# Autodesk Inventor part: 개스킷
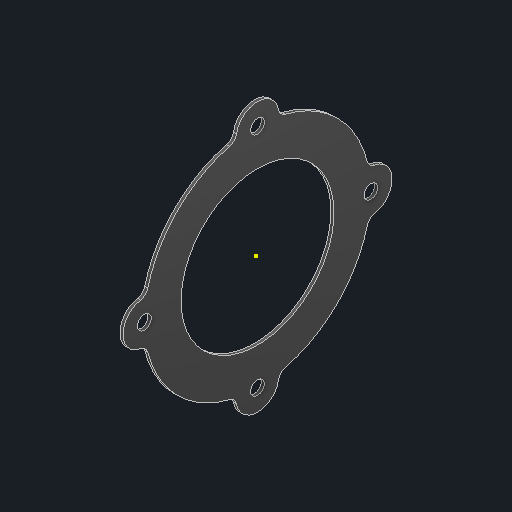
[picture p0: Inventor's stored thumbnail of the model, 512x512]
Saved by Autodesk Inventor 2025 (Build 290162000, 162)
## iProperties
Created: 2025-08
Part Number: 개스킷
Material: 황동, 연질 노란색
Document SubType Name: Modeling
Designer: infra012
Density: 8.47 g/cm^3
Appearance: 기본값
Author: jhkim
Sending System: Autodesk Inventor 2026
Preprocessor: ST-DEVELOPER v20.1
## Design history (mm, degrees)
sketch "스케치1"
  geometry: 1 further point
  constraints: 1 other
feature "솔리드2"
node "솔리드1"
